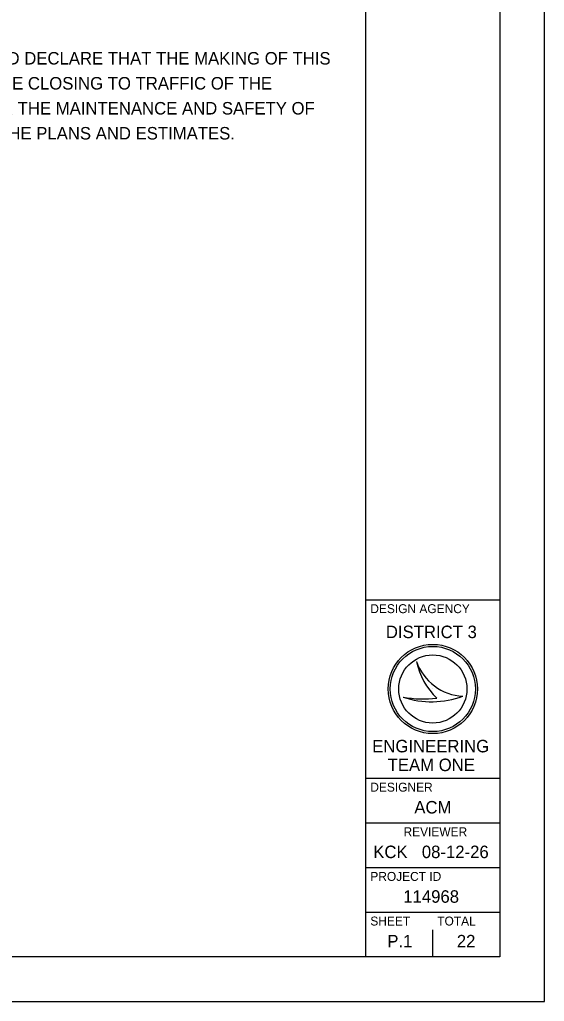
# Model space of a CAD drawing. Extents: x 0 to 34, y 0 to 22.
# Drawn here: x 28.12 to 34, y 0 to 11 of the extents above; entities that cross this region are included whole.
import ezdxf

# ---------------------------------------------------------------- set-up
doc = ezdxf.new("R2010")
doc.units = 0
for name, color, linetype in [('SH_Border', 7, 'Continuous'), ('SH_Cut_Line', 7, 'Continuous'), ('SH_Data', 7, 'Continuous'), ('SH_Text', 7, 'Continuous')]:
    doc.layers.add(name, color=color, linetype=linetype)

msp = doc.modelspace()

# ---------------------------------------------------------------- linework, layer by layer
at = {"layer": 'SH_Border'}
for p, q in [((32, 0.5), (32, 21.5)), ((32, 4.5), (33.5, 4.5)), ((32, 2.5), (33.5, 2.5)), ((32, 2), (33.5, 2)), ((32, 1.5), (33.5, 1.5)), ((32, 1), (33.5, 1))]:
    msp.add_line(p, q, dxfattribs=at)
msp.add_lwpolyline([(1.5, 21.5), (33.5, 21.5), (33.5, 0.5), (1.5, 0.5)], close=True, dxfattribs=at)
at = {"layer": 'SH_Cut_Line'}
msp.add_lwpolyline([(0, 0), (34, 0), (34, 22), (0, 22)], close=True, dxfattribs=at)
at = {"layer": 'SH_Data'}
for p, q in [((32.567, 3.81), (32.567, 3.81)), ((32.75, 3.5), (32.75, 3.5)), ((33.087, 3.419), (33.087, 3.419)), ((32.417, 3.41), (32.417, 3.41)), ((32.75, 0.5), (32.75, 0.8)), ((32.375, 0.675), (32.375, 0.675))]:
    msp.add_line(p, q, dxfattribs=at)
for radius in [0.5, 0.477, 0.477, 0.382]:
    msp.add_circle((32.75, 3.5), radius, dxfattribs=at)
for centre, radius, start, end in [((33.116, 3.998), 0.58, 198.9257, 198.9319), ((33.347, 3.97), 0.796, 191.6379, 191.6421), ((33.116, 3.998), 0.58, 198.9319, 267.1657), ((33.347, 3.97), 0.796, 191.6421, 226.0947), ((32.739, 4.37), 1.013, 251.4576, 290.0832), ((32.648, 4.654), 1.266, 259.4964, 259.4995), ((32.739, 4.37), 1.013, 251.4527, 251.4576), ((32.648, 4.654), 1.266, 259.4995, 276.6672)]:
    msp.add_arc(centre, radius, start, end, dxfattribs=at)

# ---------------------------------------------------------------- texts
for s, height, p in [('DESIGN AGENCY', 0.1, (32.05, 4.35)), ('DISTRICT 3', 0.14, (32.224, 4.07)), ('ENGINEERING', 0.14, (32.071, 2.79)), ('TEAM ONE', 0.14, (32.244, 2.58)), ('DESIGNER', 0.1, (32.05, 2.35)), ('ACM', 0.14, (32.543, 2.105)), ('REVIEWER', 0.1, (32.422, 1.85)), ('KCK', 0.14, (32.083, 1.605)), ('08-12-26', 0.14, (32.627, 1.605)), ('PROJECT ID', 0.1, (32.05, 1.35)), ('114968', 0.14, (32.419, 1.105)), ('SHEET', 0.1, (32.05, 0.85)), ('TOTAL', 0.1, (32.8, 0.85)), ('P.1', 0.14, (32.24, 0.605)), ('22', 0.14, (33.019, 0.605))]:
    msp.add_text(s, height=height, dxfattribs=at).set_placement(p)
at = {"layer": 'SH_Text'}
for s, p in [('I HEREBY APPROVE THESE PLANS AND DECLARE THAT THE MAKING OF THIS', (24.5, 10.497)), ('IMPROVEMENT WILL NOT REQUIRE THE CLOSING TO TRAFFIC OF THE ', (24.5, 10.217)), ('HIGHWAY AND THAT PROVISIONS FOR THE MAINTENANCE AND SAFETY OF', (24.5, 9.937)), ('TRAFFIC WILL BE AS SET FORTH ON THE PLANS AND ESTIMATES.', (24.5, 9.657))]:
    msp.add_text(s, height=0.14, dxfattribs=at).set_placement(p)

doc.saveas('drawing.dxf')
